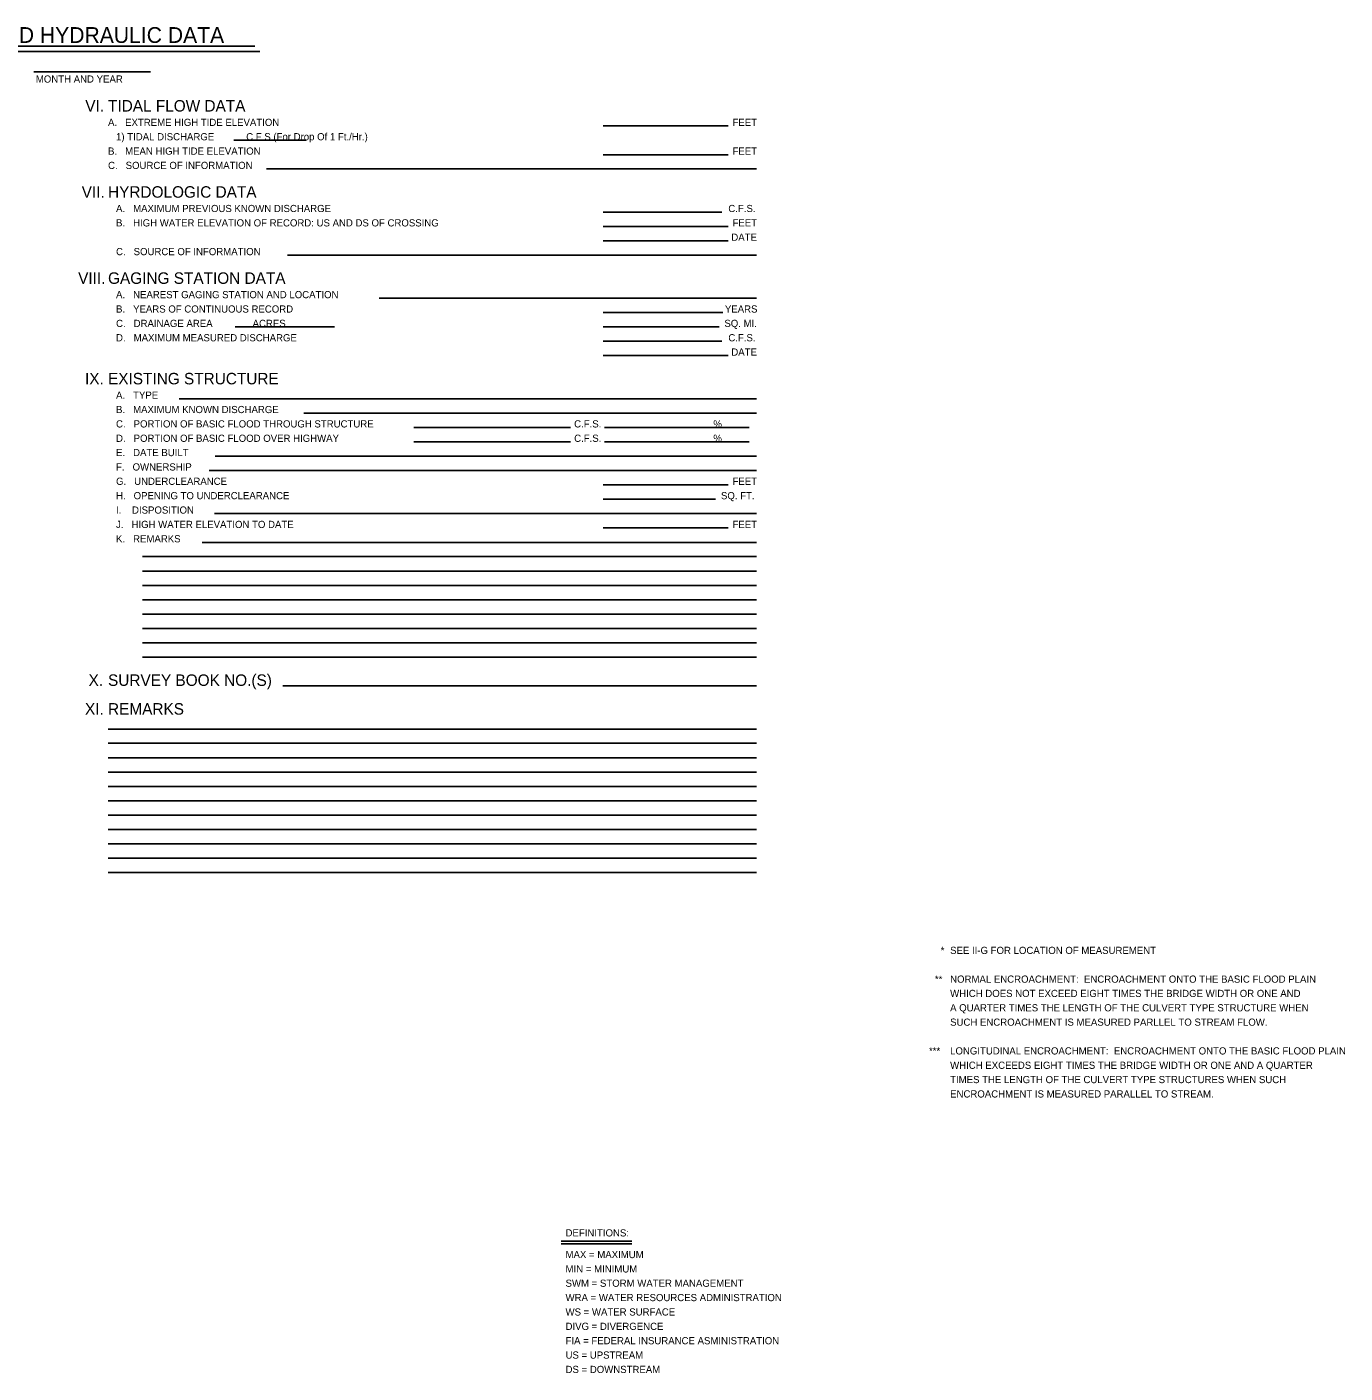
# Model space of a CAD drawing. Extents: x 3 to 31.3, y 2.1 to 20.5.
# Drawn here: x 13.21 to 31.28, y 2.08 to 20.53 of the extents above; entities that cross this region are included whole.
import ezdxf

# ---------------------------------------------------------------- set-up
doc = ezdxf.new("R2010")
doc.units = 0
doc.layers.add('G-ANNO-NOTE', color=7, linetype='Continuous')

msp = doc.modelspace()

# ---------------------------------------------------------------- linework, layer by layer
at = {"layer": 'G-ANNO-NOTE'}
for p, q in [((10.1, 20.198), (16.402, 20.198)), ((10.178, 20.27), (16.33, 20.27)), ((13.301, 19.919), (14.902, 19.919)), ((22.82, 19.177), (21.106, 19.177)), ((17.035, 18.98), (16.042, 18.98)), ((22.82, 18.783), (21.106, 18.783)), ((23.21, 18.587), (16.493, 18.587)), ((22.737, 17.996), (21.106, 17.996)), ((22.82, 17.799), (21.106, 17.799)), ((22.82, 17.602), (21.106, 17.602)), ((23.21, 17.405), (16.781, 17.405)), ((23.21, 16.815), (18.038, 16.815)), ((22.748, 16.618), (21.106, 16.618)), ((17.426, 16.421), (16.063, 16.421)), ((22.699, 16.421), (21.106, 16.421)), ((22.737, 16.224), (21.106, 16.224)), ((22.82, 16.028), (21.106, 16.028)), ((23.21, 15.437), (15.292, 15.437)), ((23.21, 15.24), (17.003, 15.24)), ((20.659, 15.043), (18.513, 15.043)), ((23.109, 15.043), (21.127, 15.043)), ((20.659, 14.846), (18.513, 14.846)), ((23.109, 14.846), (21.127, 14.846)), ((23.21, 14.65), (15.788, 14.65)), ((23.21, 14.453), (15.704, 14.453)), ((22.82, 14.256), (21.106, 14.256)), ((22.65, 14.059), (21.106, 14.059)), ((23.21, 13.862), (15.778, 13.862)), ((22.82, 13.665), (21.106, 13.665)), ((23.21, 13.468), (15.609, 13.468)), ((23.21, 13.272), (14.793, 13.272)), ((23.21, 13.075), (14.793, 13.075)), ((23.21, 12.878), (14.793, 12.878)), ((23.21, 12.681), (14.793, 12.681)), ((23.21, 12.484), (14.793, 12.484)), ((23.21, 12.287), (14.793, 12.287)), ((23.21, 12.091), (14.793, 12.091)), ((23.21, 11.894), (14.793, 11.894)), ((23.21, 11.5), (16.717, 11.5)), ((23.21, 10.909), (14.319, 10.909)), ((23.21, 10.713), (14.319, 10.713)), ((23.21, 10.516), (14.319, 10.516)), ((23.21, 10.319), (14.319, 10.319)), ((23.21, 10.122), (14.319, 10.122)), ((23.21, 9.925), (14.319, 9.925)), ((23.21, 9.728), (14.319, 9.728)), ((23.21, 9.531), (14.319, 9.531)), ((23.21, 9.335), (14.319, 9.335)), ((23.21, 9.138), (14.319, 9.138)), ((23.21, 8.941), (14.319, 8.941)), ((20.53, 3.887), (21.501, 3.887)), ((20.53, 3.852), (21.501, 3.852))]:
    msp.add_line(p, q, dxfattribs=at)

# ---------------------------------------------------------------- texts
for s, height, p in [('HYDROLOGIC AND HYDRAULIC DATA', 0.21654, (10.666, 20.315)), ('  MONTH AND YEAR', 0.09843, (13.256, 19.771)), ('VI.  ', 0.1575, (14.007, 19.374)), ('TIDAL FLOW DATA', 0.15748, (14.319, 19.374)), ('A.   EXTREME HIGH TIDE ELEVATION', 0.09843, (14.319, 19.177)), ('FEET', 0.0984, (22.881, 19.177)), ('   1) TIDAL DISCHARGE            C.F.S.(For Drop Of 1 Ft./Hr.)', 0.09843, (14.319, 18.98)), ('B.   MEAN HIGH TIDE ELEVATION', 0.09843, (14.319, 18.783)), ('FEET', 0.0984, (22.881, 18.783)), ('C.   SOURCE OF INFORMATION', 0.09843, (14.319, 18.587)), ('VII.  ', 0.1575, (13.958, 18.193)), ('HYRDOLOGIC DATA', 0.15748, (14.319, 18.193)), ('   A.   MAXIMUM PREVIOUS KNOWN DISCHARGE', 0.09843, (14.319, 17.996)), ('C.F.S.', 0.0984, (22.824, 17.996)), ('   B.   HIGH WATER ELEVATION OF RECORD: US AND DS OF CROSSING', 0.09843, (14.319, 17.799)), ('FEET', 0.0984, (22.881, 17.799)), ('DATE', 0.0984, (22.865, 17.602)), ('   C.   SOURCE OF INFORMATION', 0.09843, (14.319, 17.405)), ('VIII.  ', 0.1575, (13.909, 17.012)), ('GAGING STATION DATA', 0.15748, (14.319, 17.012)), ('   A.   NEAREST GAGING STATION AND LOCATION', 0.09843, (14.319, 16.815)), ('   B.   YEARS OF CONTINUOUS RECORD', 0.09843, (14.319, 16.618)), ('YEARS', 0.0984, (22.777, 16.618)), ('   C.   DRAINAGE AREA               ACRES ', 0.09843, (14.319, 16.421)), ('SQ. MI.', 0.0984, (22.77, 16.421)), ('   D.   MAXIMUM MEASURED DISCHARGE', 0.09843, (14.319, 16.224)), ('C.F.S.', 0.0984, (22.824, 16.224)), ('DATE', 0.0984, (22.865, 16.028)), ('IX.  ', 0.1575, (14.003, 15.634)), ('EXISTING STRUCTURE', 0.15748, (14.319, 15.634)), ('   A.   TYPE', 0.09843, (14.319, 15.437)), ('   B.   MAXIMUM KNOWN DISCHARGE', 0.09843, (14.319, 15.24)), ('   C.   PORTION OF BASIC FLOOD THROUGH STRUCTURE', 0.09843, (14.319, 15.043)), ('C.F.S.                                          %', 0.09843, (20.71, 15.043)), ('   D.   PORTION OF BASIC FLOOD OVER HIGHWAY', 0.09843, (14.319, 14.846)), ('C.F.S.                                          %', 0.09843, (20.71, 14.846)), ('   E.   DATE BUILT', 0.09843, (14.319, 14.65)), ('   F.   OWNERSHIP', 0.09843, (14.319, 14.453)), ('   G.   UNDERCLEARANCE', 0.09843, (14.319, 14.256)), ('FEET', 0.0984, (22.881, 14.256)), ('   H.   OPENING TO UNDERCLEARANCE', 0.09843, (14.319, 14.059)), ('SQ. FT.', 0.0984, (22.723, 14.059)), ('   I.    DISPOSITION', 0.09843, (14.319, 13.862)), ('   J.   HIGH WATER ELEVATION TO DATE', 0.09843, (14.319, 13.665)), ('FEET', 0.0984, (22.881, 13.665)), ('   K.   REMARKS', 0.09843, (14.319, 13.468)), ('X.  ', 0.1575, (14.052, 11.5)), ('SURVEY BOOK NO.(S)', 0.15748, (14.319, 11.5)), ('XI.  ', 0.1575, (14.003, 11.106)), ('REMARKS', 0.1575, (14.319, 11.106)), ('* ', 0.0984, (25.736, 7.825)), ('SEE II-G FOR LOCATION OF MEASUREMENT', 0.09843, (25.865, 7.825)), ('** ', 0.0984, (25.656, 7.431)), ('NORMAL ENCROACHMENT:  ENCROACHMENT ONTO THE BASIC FLOOD PLAIN ', 0.09843, (25.865, 7.431)), ('WHICH DOES NOT EXCEED EIGHT TIMES THE BRIDGE WIDTH OR ONE AND', 0.09843, (25.865, 7.235)), ('A QUARTER TIMES THE LENGTH OF THE CULVERT TYPE STRUCTURE WHEN', 0.09843, (25.865, 7.038)), ('SUCH ENCROACHMENT IS MEASURED PARLLEL TO STREAM FLOW.', 0.09843, (25.865, 6.841)), ('*** ', 0.0984, (25.575, 6.447)), ('LONGITUDINAL ENCROACHMENT:  ENCROACHMENT ONTO THE BASIC FLOOD PLAIN', 0.09843, (25.865, 6.447)), ('WHICH EXCEEDS EIGHT TIMES THE BRIDGE WIDTH OR ONE AND A QUARTER', 0.09843, (25.865, 6.25)), ('TIMES THE LENGTH OF THE CULVERT TYPE STRUCTURES WHEN SUCH', 0.09843, (25.865, 6.054)), ('ENCROACHMENT IS MEASURED PARALLEL TO STREAM.', 0.09843, (25.865, 5.857)), ('DEFINITIONS:', 0.09843, (20.592, 3.952)), ('MAX = MAXIMUM', 0.09843, (20.592, 3.655)), ('MIN = MINIMUM', 0.09843, (20.592, 3.458)), ('SWM = STORM WATER MANAGEMENT', 0.09843, (20.592, 3.262)), ('WRA = WATER RESOURCES ADMINISTRATION', 0.09843, (20.592, 3.065)), ('WS = WATER SURFACE', 0.09843, (20.592, 2.868)), ('DIVG = DIVERGENCE', 0.09843, (20.592, 2.671)), ('FIA = FEDERAL INSURANCE ASMINISTRATION', 0.09843, (20.592, 2.474)), ('US = UPSTREAM', 0.09843, (20.592, 2.277)), ('DS = DOWNSTREAM', 0.09843, (20.592, 2.08))]:
    msp.add_text(s, height=height, dxfattribs=at).set_placement(p)

doc.saveas('drawing.dxf')
